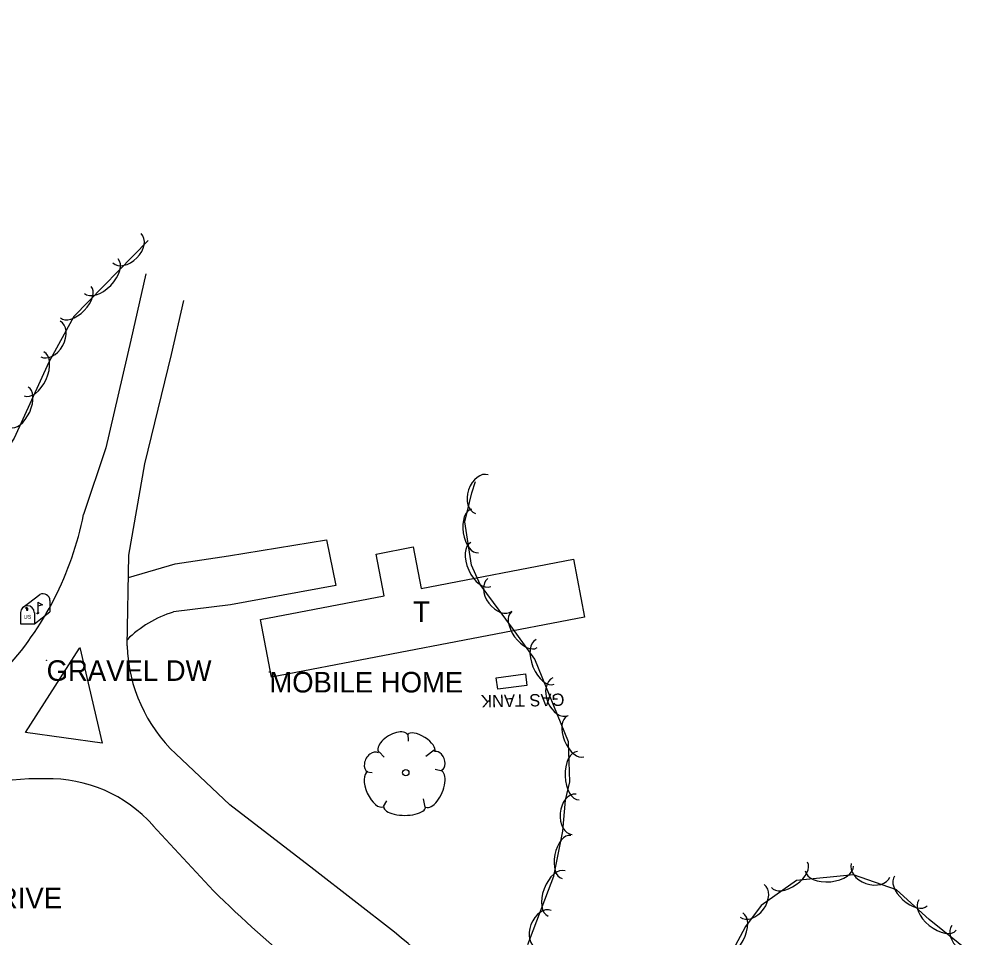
# Model space of a CAD drawing. Extents: x 954793 to 988390, y 1867850 to 1924428.
# Drawn here: x 966866.3 to 967101, y 1897336.4 to 1897559.8 of the extents above; entities that cross this region are included whole.
import ezdxf

# ---------------------------------------------------------------- set-up
doc = ezdxf.new("R2010")
doc.units = 0
for name, color, linetype in [('S_BUILDING', 7, 'Continuous'), ('S_BUILDING_ANNOT', 7, 'Continuous'), ('S_DRIVEWAY', 7, 'Continuous'), ('S_GRAVEL_ROAD', 7, 'Continuous'), ('S_MAILBOX', 7, 'Continuous'), ('S_MSC_PT_SYM', 7, 'Continuous'), ('S_SIGN_ANNOT', 7, 'Continuous'), ('S_SURVEY_TEXT_ANNOT', 7, 'Continuous'), ('S_TANK', 7, 'Continuous'), ('S_TANK_ANNOT', 7, 'Continuous'), ('S_TREE', 7, 'Continuous')]:
    doc.layers.add(name, color=color, linetype=linetype)

msp = doc.modelspace()

# ---------------------------------------------------------------- linework, layer by layer
at = {"layer": 'S_BUILDING'}
msp.add_lwpolyline([(967003.86, 1897414.35), (966927.7, 1897399.82), (966925.03, 1897413.82), (966955.14, 1897419.56), (966953.2, 1897429.73), (966962.17, 1897431.44), (966964.1, 1897421.37), (967001.17, 1897428.45)], close=True, dxfattribs=at)
at = {"layer": 'S_DRIVEWAY'}
msp.add_lwpolyline([(966892.95, 1897424.03), (966904.29, 1897427.36), (966917.29, 1897429.3), (966941.07, 1897433.18), (966943.38, 1897422.06), (966917.77, 1897417.39), (966903.83, 1897415.63)], dxfattribs=at)
msp.add_ellipse((966911.44, 1897390.15), major_axis=(-23.84, -13.27), ratio=0.97313, start_param=4.50057, end_param=4.986184, dxfattribs=at)
at = {"layer": 'S_GRAVEL_ROAD'}
for points in [[(966897.15, 1897497.84), (966893.52, 1897481.77), (966887.42, 1897455.57), (966881.99, 1897439.31)], [(966892.57, 1897407.36), (966893.04, 1897429.46), (966896.92, 1897451.65), (966903.4, 1897478.23), (966906.39, 1897491.36)], [(966881.04, 1897406.96), (966886.54, 1897383.73), (966867.89, 1897386.36), (966881.02, 1897406.81)], [(966957.61, 1897337.78), (966938.04, 1897352.99), (966917.55, 1897368.71), (966904.42, 1897381.16)], [(966898.88, 1897363.72), (966913.58, 1897347.84)]]:
    msp.add_lwpolyline(points, dxfattribs=at)
for centre, major_axis, ratio, start_param, end_param in [((966805.23, 1897454.19), (58.94, 51.74), 0.995059, 4.813857, 5.368861), ((966930.27, 1897408.43), (30.71, -22.02), 0.994325, 3.794745, 4.57657), ((966870.99, 1897320.45), (-25.98, 48.06), 0.999111, 5.755126, 6.35205), ((966873.6, 1897341.17), (11.29, 31.96), 0.997449, 5.779136, 6.648724), ((967126.85, 1897562.81), (291.66, -84.14), 0.996805, 4.21319, 4.407447), ((966904.86, 1897270.38), (-25.42, 81.77), 0.999207, 4.910969, 5.31744)]:
    msp.add_ellipse(centre, major_axis=major_axis, ratio=ratio, start_param=start_param, end_param=end_param, dxfattribs=at)
at = {"layer": 'S_MAILBOX'}
for p, q in [((966867.24, 1897416.76), (966871.37, 1897419.87)), ((966870.85, 1897418.05), (966870.85, 1897415.34)), ((966873.8, 1897418.4), (966873.8, 1897415.68)), ((966866.68, 1897415.49), (966866.68, 1897412.77)), ((966870.01, 1897412.77), (966873.8, 1897415.68)), ((966870.01, 1897415.49), (966870.01, 1897412.77)), ((966866.68, 1897412.77), (966870.01, 1897412.77))]:
    msp.add_line(p, q, dxfattribs=at)
for points in [[(966867.87, 1897416.6), (966868.09, 1897416.47), (966868.09, 1897416.08), (966868.39, 1897416.08), (966868.39, 1897416.44), (966868.2, 1897416.69), (966867.87, 1897416.63)], [(966870.85, 1897418.05), (966871.96, 1897417.39), (966870.85, 1897417.04)]]:
    msp.add_lwpolyline(points, dxfattribs=at)
for centre, end in [((966872.14, 1897418.4), 117.5718), ((966868.34, 1897415.49), 180)]:
    msp.add_arc(centre, 1.66, 0, end, dxfattribs=at)
msp.add_ellipse((966870.85, 1897415.34), major_axis=(0.145, 0.132), ratio=0.564646, dxfattribs=at)
at = {"layer": 'S_MSC_PT_SYM'}
for points in [[(966873, 1897403.88), (966873, 1897403.93), (966873, 1897403.88), (966872.95, 1897403.88), (966873, 1897403.88), (966873, 1897403.83), (966873, 1897403.88), (966873.05, 1897403.88)], [(966927.18, 1897401.06), (966927.18, 1897401.11), (966927.18, 1897401.06), (966927.13, 1897401.06), (966927.18, 1897401.06), (966927.18, 1897401.01), (966927.18, 1897401.06), (966927.23, 1897401.06)]]:
    msp.add_lwpolyline(points, dxfattribs=at)
at = {"layer": 'S_TANK'}
msp.add_lwpolyline([(966989.87, 1897397.76), (966982.77, 1897396.83), (966982.39, 1897399.65), (966989.49, 1897400.59)], close=True, dxfattribs=at)
at = {"layer": 'S_TREE'}
for p, q in [((966960.87, 1897386.12), (966960.98, 1897384.24)), ((966953.9, 1897381.62), (966955.09, 1897380.34)), ((966967.26, 1897381.99), (966965.24, 1897380.47)), ((966950.8, 1897376.77), (966952.21, 1897376.63)), ((966969.23, 1897376.92), (966967.53, 1897377.29)), ((966954.97, 1897368.35), (966955.78, 1897369.73)), ((966965.14, 1897368.17), (966964.68, 1897370.22))]:
    msp.add_line(p, q, dxfattribs=at)
for points in [[(966897.72, 1897506.01), (966879.64, 1897487.46), (966873.55, 1897476.36), (966865.14, 1897457.89), (966853.4, 1897440.16), (966840.2, 1897432.14), (966833.53, 1897432.05), (966814.47, 1897447.9), (966787.24, 1897478.16), (966774.26, 1897488.94), (966766.47, 1897503.01), (966767.61, 1897514.52), (966775.97, 1897527.66), (966783.8, 1897537.15), (966789.38, 1897541.01), (966805.13, 1897550.04), (966818.68, 1897557.32), (966827.41, 1897559.76), (966838.8, 1897558.04), (966848.94, 1897552.9)], [(966990.1, 1897334.77), (966996.38, 1897351.41), (966998.57, 1897362.33), (966999.28, 1897369.85), (967000.29, 1897374.32), (966999.96, 1897384.05), (966991.76, 1897404.14), (966986.32, 1897411.69), (966978.5, 1897422.3), (966976.37, 1897427.02), (966974.73, 1897437.56), (966976.49, 1897444.63), (966977.39, 1897447.34)], [(967098.08, 1897332.51), (967087.74, 1897340.83), (967079.8, 1897348.07), (967069.34, 1897351.73), (967055.42, 1897350.3), (967046.84, 1897344.28), (967043.03, 1897339.12), (967036.72, 1897327.35)]]:
    msp.add_lwpolyline(points, dxfattribs=at)
msp.add_circle((966960.39, 1897376.54), 0.765, dxfattribs=at)
for centre, major_axis, ratio, start_param, end_param in [((966892.55, 1897504.12), (3.46, 3.55), 0.685311, 3.141593, 6.283185), ((966886.28, 1897497.31), (4.09, 4.2), 0.55008, 3.141593, 6.283185), ((966880.09, 1897490.96), (3.73, 3.83), 0.540699, 3.141593, 6.283185), ((966873.95, 1897482.04), (2.38, 4.34), 0.685311, 3.141593, 6.283185), ((966869.93, 1897473.52), (2.43, 5.34), 0.55008, 3.141593, 6.283185), ((966866.25, 1897465.45), (2.22, 4.87), 0.540699, 3.141593, 6.283185), ((966978.89, 1897444.28), (-1.56, -4.7), 0.685311, 3.141593, 6.283185), ((966977.22, 1897435.32), (0.82, -5.28), 0.540699, 3.141593, 6.283185), ((966978.64, 1897427.16), (2.41, -5.35), 0.55008, 3.141593, 6.283185), ((966983.31, 1897419.79), (2.94, -3.99), 0.685311, 3.141593, 6.283185), ((966989.21, 1897411.3), (3.13, -4.34), 0.540699, 3.141593, 6.283185), ((966994.31, 1897403.49), (2.22, -5.43), 0.55008, 3.141593, 6.283185), ((966998.06, 1897395.02), (1.87, -4.59), 0.685311, 3.141593, 6.283185), ((967001.71, 1897385.38), (2.02, -4.95), 0.540699, 3.141593, 6.283185), ((966957.31, 1897383.63), (3.55, 2.13), 0.529943, 0, 3.141593), ((966964.14, 1897383.77), (3.26, -2.04), 0.420543, 6.283185, 9.424777), ((966952.4, 1897379.1), (-1.33, -2.31), 0.711534, 3.141592, 6.283185), ((966968.27, 1897379.42), (0.84, -2.26), 0.646762, 0, 3.141593), ((967002.36, 1897375.83), (0.2, -5.87), 0.55008, 3.141593, 6.283185), ((966953.08, 1897372.52), (1.94, -4.28), 0.482994, 3.141593, 6.283185), ((966967.13, 1897372.61), (-1.86, -4.46), 0.471018, 0, 3.141593), ((967001.34, 1897366.41), (-0.47, -4.93), 0.685311, 3.141593, 6.283185), ((966960.13, 1897368.24), (5.09, 0.01), 0.405113, 3.141593, 6.283186), ((966999.47, 1897356.05), (-1.05, -5.24), 0.540699, 3.141593, 6.283185), ((966997.06, 1897347.18), (-2.07, -5.49), 0.55008, 3.141593, 6.283185), ((967053.72, 1897351.7), (4.38, 3.07), 0.540699, 3.141593, 6.283185), ((967063.44, 1897353.25), (5.84, 0.6), 0.55008, 3.141593, 6.283185), ((967073.47, 1897352.81), (4.68, -1.63), 0.685311, 3.141593, 6.283185), ((967083.28, 1897347.77), (3.95, -3.6), 0.540699, 3.141593, 6.283185), ((967044.68, 1897345.37), (2.94, 3.99), 0.685311, 3.141593, 6.283185), ((967089.77, 1897341.92), (4.57, -3.68), 0.55008, 3.141593, 6.283185), ((966994.03, 1897338.43), (-1.75, -4.64), 0.685311, 3.141593, 6.283185), ((967039.62, 1897337.26), (2.77, 5.17), 0.55008, 3.141593, 6.283185), ((967097.14, 1897336.32), (3.86, -3.11), 0.685311, 3.141593, 6.283185)]:
    msp.add_ellipse(centre, major_axis=major_axis, ratio=ratio, start_param=start_param, end_param=end_param, dxfattribs=at)

# ---------------------------------------------------------------- texts
at = {"layer": 'S_BUILDING_ANNOT'}
msp.add_text('T', height=5, dxfattribs=at).set_placement((966962.15, 1897413.23))
at = {"layer": 'S_MAILBOX'}
msp.add_text('US', height=0.96, rotation=360, dxfattribs=at).set_placement((966867.44, 1897413.97))
at = {"layer": 'S_SIGN_ANNOT'}
msp.add_text('0 TO POST TY:M/W EDGEWOOD CADDO DRIVE', height=5, dxfattribs=at).set_placement((966725.19, 1897343.57))
at = {"layer": 'S_SURVEY_TEXT_ANNOT'}
for s, p in [('GRAVEL DW', (966873, 1897398.88)), ('MOBILE HOME', (966927.18, 1897396.06))]:
    msp.add_text(s, height=5, dxfattribs=at).set_placement(p)
at = {"layer": 'S_TANK_ANNOT'}
msp.add_text('GAS TANK', height=3, rotation=181.1545, dxfattribs=at).set_placement((966998.95, 1897395.82))

doc.saveas('drawing.dxf')
